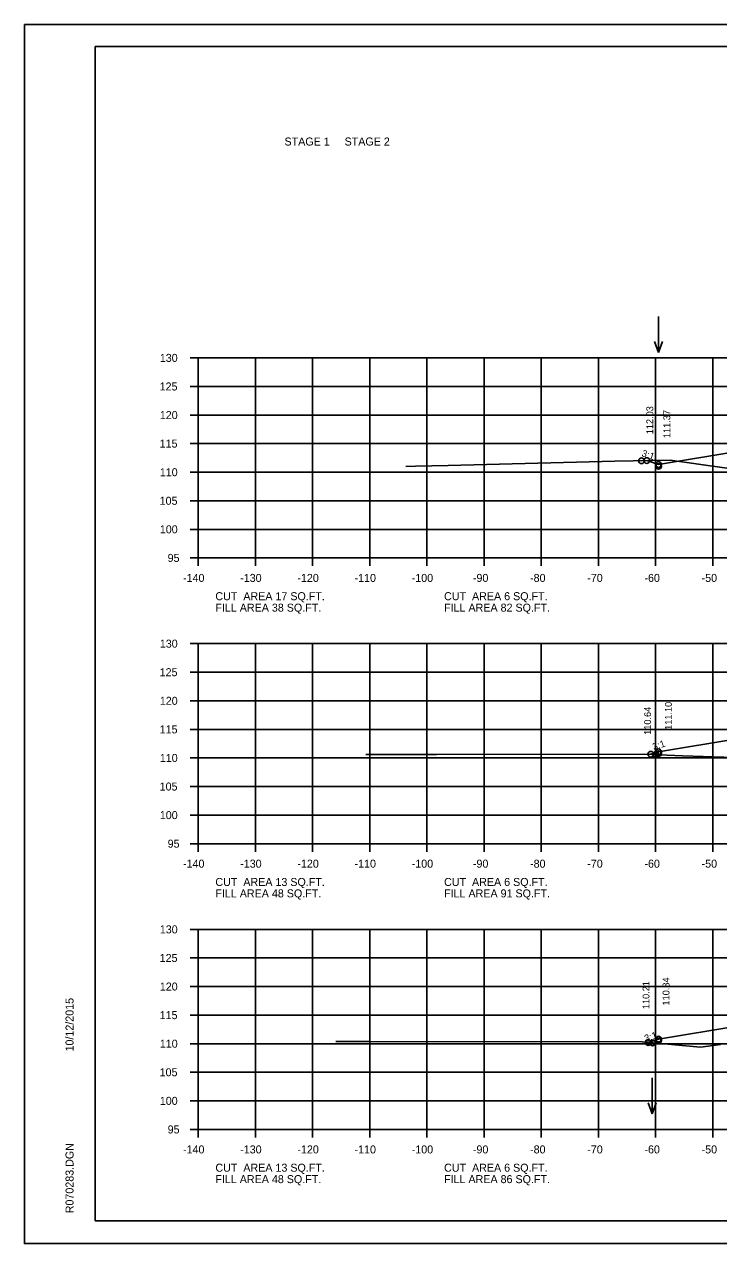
# Model space of a CAD drawing. Extents: x 1175611 to 1176402, y -433344 to -416213.
# Drawn here: x 1175610.6 to 1175732, y -421823.3 to -421609.9 of the extents above; entities that cross this region are included whole.
import ezdxf

# ---------------------------------------------------------------- set-up
doc = ezdxf.new("R2010")
doc.units = 0
for name, color, linetype in [('Default', 7, 'Continuous'), ('R_Axis', 7, 'Continuous'), ('R_Axis Annot', 7, 'Continuous'), ('R_Border', 7, 'Continuous'), ('R_Exist Surface', 7, 'Continuous'), ('R_Fin Surface', 7, 'Continuous'), ('R_Grid', 7, 'Continuous'), ('R_No Plot', 7, 'Continuous'), ('R_Water Annot', 7, 'Continuous'), ('R_Xsect Elev', 7, 'Continuous'), ('R_Xsect Slope', 7, 'Continuous')]:
    doc.layers.add(name, color=color, linetype=linetype)

msp = doc.modelspace()

# ---------------------------------------------------------------- linework, layer by layer
at = {"layer": 'R_Axis'}
for p, q in [((1175639.57, -421668.3), (1175640.97, -421668.3)), ((1175640.97, -421703.3), (1175640.97, -421668.3)), ((1175639.57, -421673.3), (1175640.97, -421673.3)), ((1175639.57, -421678.3), (1175640.97, -421678.3)), ((1175639.57, -421683.3), (1175640.97, -421683.3)), ((1175639.57, -421688.3), (1175640.97, -421688.3)), ((1175639.57, -421693.3), (1175640.97, -421693.3)), ((1175639.57, -421698.3), (1175640.97, -421698.3)), ((1175639.57, -421703.3), (1175640.97, -421703.3)), ((1175640.97, -421703.3), (1175920.97, -421703.3)), ((1175640.97, -421704.7), (1175640.97, -421703.3)), ((1175650.97, -421704.7), (1175650.97, -421703.3)), ((1175660.97, -421704.7), (1175660.97, -421703.3)), ((1175670.97, -421704.7), (1175670.97, -421703.3)), ((1175680.97, -421704.7), (1175680.97, -421703.3)), ((1175690.97, -421704.7), (1175690.97, -421703.3)), ((1175700.97, -421704.7), (1175700.97, -421703.3)), ((1175710.97, -421704.7), (1175710.97, -421703.3)), ((1175720.97, -421704.7), (1175720.97, -421703.3)), ((1175730.97, -421704.7), (1175730.97, -421703.3)), ((1175639.57, -421718.3), (1175640.97, -421718.3)), ((1175640.97, -421753.3), (1175640.97, -421718.3)), ((1175639.57, -421723.3), (1175640.97, -421723.3)), ((1175639.57, -421728.3), (1175640.97, -421728.3)), ((1175639.57, -421733.3), (1175640.97, -421733.3)), ((1175639.57, -421738.3), (1175640.97, -421738.3)), ((1175639.57, -421743.3), (1175640.97, -421743.3)), ((1175639.57, -421748.3), (1175640.97, -421748.3)), ((1175639.57, -421753.3), (1175640.97, -421753.3)), ((1175640.97, -421753.3), (1175920.97, -421753.3)), ((1175640.97, -421754.7), (1175640.97, -421753.3)), ((1175650.97, -421754.7), (1175650.97, -421753.3)), ((1175660.97, -421754.7), (1175660.97, -421753.3)), ((1175670.97, -421754.7), (1175670.97, -421753.3)), ((1175680.97, -421754.7), (1175680.97, -421753.3)), ((1175690.97, -421754.7), (1175690.97, -421753.3)), ((1175700.97, -421754.7), (1175700.97, -421753.3)), ((1175710.97, -421754.7), (1175710.97, -421753.3)), ((1175720.97, -421754.7), (1175720.97, -421753.3)), ((1175730.97, -421754.7), (1175730.97, -421753.3)), ((1175639.57, -421768.3), (1175640.97, -421768.3)), ((1175640.97, -421803.3), (1175640.97, -421768.3)), ((1175639.57, -421773.3), (1175640.97, -421773.3)), ((1175639.57, -421778.3), (1175640.97, -421778.3)), ((1175639.57, -421783.3), (1175640.97, -421783.3)), ((1175639.57, -421788.3), (1175640.97, -421788.3)), ((1175639.57, -421793.3), (1175640.97, -421793.3)), ((1175639.57, -421798.3), (1175640.97, -421798.3)), ((1175639.57, -421803.3), (1175640.97, -421803.3)), ((1175640.97, -421803.3), (1175920.97, -421803.3)), ((1175640.97, -421804.7), (1175640.97, -421803.3)), ((1175650.97, -421804.7), (1175650.97, -421803.3)), ((1175660.97, -421804.7), (1175660.97, -421803.3)), ((1175670.97, -421804.7), (1175670.97, -421803.3)), ((1175680.97, -421804.7), (1175680.97, -421803.3)), ((1175690.97, -421804.7), (1175690.97, -421803.3)), ((1175700.97, -421804.7), (1175700.97, -421803.3)), ((1175710.97, -421804.7), (1175710.97, -421803.3)), ((1175720.97, -421804.7), (1175720.97, -421803.3)), ((1175730.97, -421804.7), (1175730.97, -421803.3))]:
    msp.add_line(p, q, dxfattribs=at)
at = {"layer": 'R_Border'}
for p, q in [((1175622.97, -421613.84), (1175939.15, -421613.84)), ((1175622.97, -421819.3), (1175622.97, -421613.84)), ((1175622.97, -421819.3), (1175622.97, -421819.3)), ((1175939.15, -421819.3), (1175622.97, -421819.3))]:
    msp.add_line(p, q, dxfattribs=at)
at = {"layer": 'R_Exist Surface'}
for points in [[(1175677.28, -421687.29), (1175678.96, -421687.26), (1175684.7, -421687.12), (1175713.84, -421686.38), (1175723.49, -421686.18), (1175733.41, -421687.61)], [(1175670.26, -421737.68), (1175670.42, -421737.68), (1175675.91, -421737.68), (1175682.64, -421737.67), (1175718.96, -421737.61), (1175725.69, -421737.92), (1175734.69, -421738.22)], [(1175665.01, -421787.92), (1175670.42, -421787.9), (1175670.5, -421787.9), (1175671.12, -421787.9), (1175718.6, -421787.99), (1175719.28, -421788.06), (1175728.82, -421788.92), (1175731.91, -421788.48), (1175732.3, -421788.42)]]:
    msp.add_lwpolyline(points, dxfattribs=at)
at = {"layer": 'R_Fin Surface'}
for points in [[(1175719.41, -421686.26), (1175721.47, -421686.95), (1175735.2, -421684.66), (1175743.47, -421683.29), (1175749.47, -421683.05), (1175751.47, -421683.01), (1175780.97, -421682.42), (1175810.47, -421683.01), (1175812.47, -421683.05), (1175818.47, -421683.29), (1175826.75, -421684.66), (1175840.47, -421686.95), (1175841.4, -421687.26)], [(1175720.13, -421737.66), (1175721.47, -421737.22), (1175735.2, -421734.93), (1175743.47, -421733.55), (1175749.47, -421733.31), (1175751.47, -421733.27), (1175780.97, -421732.68), (1175810.47, -421733.27), (1175812.47, -421733.31), (1175818.47, -421733.55), (1175826.75, -421734.93), (1175840.47, -421737.22), (1175842.06, -421737.74)], [(1175719.68, -421788.09), (1175721.47, -421787.5), (1175735.2, -421785.21), (1175743.47, -421783.83), (1175749.47, -421783.59), (1175751.47, -421783.55), (1175780.97, -421782.96), (1175810.47, -421783.55), (1175812.47, -421783.59), (1175818.47, -421783.83), (1175826.75, -421785.21), (1175840.47, -421787.5), (1175841.57, -421787.86)]]:
    msp.add_lwpolyline(points, dxfattribs=at)
at = {"layer": 'R_Grid'}
for p, q in [((1175640.97, -421668.3), (1175920.97, -421668.3)), ((1175640.97, -421703.3), (1175640.97, -421668.3)), ((1175650.97, -421703.3), (1175650.97, -421668.3)), ((1175660.97, -421703.3), (1175660.97, -421668.3)), ((1175670.97, -421703.3), (1175670.97, -421668.3)), ((1175680.97, -421703.3), (1175680.97, -421668.3)), ((1175690.97, -421703.3), (1175690.97, -421668.3)), ((1175700.97, -421703.3), (1175700.97, -421668.3)), ((1175710.97, -421703.3), (1175710.97, -421668.3)), ((1175720.97, -421703.3), (1175720.97, -421668.3)), ((1175730.97, -421703.3), (1175730.97, -421668.3)), ((1175640.97, -421673.3), (1175920.97, -421673.3)), ((1175640.97, -421678.3), (1175920.97, -421678.3)), ((1175640.97, -421683.3), (1175920.97, -421683.3)), ((1175640.97, -421688.3), (1175920.97, -421688.3)), ((1175640.97, -421693.3), (1175920.97, -421693.3)), ((1175640.97, -421698.3), (1175920.97, -421698.3)), ((1175640.97, -421703.3), (1175920.97, -421703.3)), ((1175640.97, -421718.3), (1175920.97, -421718.3)), ((1175640.97, -421753.3), (1175640.97, -421718.3)), ((1175650.97, -421753.3), (1175650.97, -421718.3)), ((1175660.97, -421753.3), (1175660.97, -421718.3)), ((1175670.97, -421753.3), (1175670.97, -421718.3)), ((1175680.97, -421753.3), (1175680.97, -421718.3)), ((1175690.97, -421753.3), (1175690.97, -421718.3)), ((1175700.97, -421753.3), (1175700.97, -421718.3)), ((1175710.97, -421753.3), (1175710.97, -421718.3)), ((1175720.97, -421753.3), (1175720.97, -421718.3)), ((1175730.97, -421753.3), (1175730.97, -421718.3)), ((1175640.97, -421723.3), (1175920.97, -421723.3)), ((1175640.97, -421728.3), (1175920.97, -421728.3)), ((1175640.97, -421733.3), (1175920.97, -421733.3)), ((1175640.97, -421738.3), (1175920.97, -421738.3)), ((1175640.97, -421743.3), (1175920.97, -421743.3)), ((1175640.97, -421748.3), (1175920.97, -421748.3)), ((1175640.97, -421753.3), (1175920.97, -421753.3)), ((1175640.97, -421768.3), (1175920.97, -421768.3)), ((1175640.97, -421803.3), (1175640.97, -421768.3)), ((1175650.97, -421803.3), (1175650.97, -421768.3)), ((1175660.97, -421803.3), (1175660.97, -421768.3)), ((1175670.97, -421803.3), (1175670.97, -421768.3)), ((1175680.97, -421803.3), (1175680.97, -421768.3)), ((1175690.97, -421803.3), (1175690.97, -421768.3)), ((1175700.97, -421803.3), (1175700.97, -421768.3)), ((1175710.97, -421803.3), (1175710.97, -421768.3)), ((1175720.97, -421803.3), (1175720.97, -421768.3)), ((1175730.97, -421803.3), (1175730.97, -421768.3)), ((1175640.97, -421773.3), (1175920.97, -421773.3)), ((1175640.97, -421778.3), (1175920.97, -421778.3)), ((1175640.97, -421783.3), (1175920.97, -421783.3)), ((1175640.97, -421788.3), (1175920.97, -421788.3)), ((1175640.97, -421793.3), (1175920.97, -421793.3)), ((1175640.97, -421798.3), (1175920.97, -421798.3)), ((1175640.97, -421803.3), (1175920.97, -421803.3))]:
    msp.add_line(p, q, dxfattribs=at)
at = {"layer": 'R_No Plot'}
for p, q in [((1175610.57, -421609.94), (1175943.91, -421609.94)), ((1175610.57, -421823.28), (1175943.91, -421823.28))]:
    msp.add_line(p, q, dxfattribs=at)
msp.add_lwpolyline([(1175610.57, -421609.94), (1175943.91, -421609.94), (1175943.91, -421823.28), (1175610.57, -421823.28)], close=True, dxfattribs=at)
for centre in [(1175718.49, -421686.29), (1175719.41, -421686.26), (1175719.41, -421686.26), (1175721.47, -421686.95), (1175721.47, -421687.28), (1175720.13, -421737.66), (1175720.13, -421737.66), (1175721, -421737.7), (1175721, -421737.7), (1175721.47, -421737.22), (1175721.47, -421737.55), (1175719.68, -421788.09), (1175719.68, -421788.09), (1175721.47, -421787.5), (1175721.47, -421787.81), (1175720.43, -421788.16)]:
    msp.add_circle(centre, 0.5, dxfattribs=at)
at = {"layer": 'R_Water Annot'}
for p, q in [((1175721.46, -421661.07), (1175721.46, -421667.36)), ((1175721.46, -421667.36), (1175720.76, -421665.43)), ((1175721.46, -421667.36), (1175722.16, -421665.43)), ((1175720.35, -421794.29), (1175720.35, -421800.58)), ((1175720.35, -421800.58), (1175719.65, -421798.65)), ((1175720.35, -421800.58), (1175721.05, -421798.65))]:
    msp.add_line(p, q, dxfattribs=at)

# ---------------------------------------------------------------- texts
at = {"layer": 'Default'}
for s, p in [('STAGE 1     STAGE 2', (1175656.06, -421631.14)), ('CUT  AREA 17 SQ.FT.', (1175643.97, -421710.7)), ('CUT  AREA 6 SQ.FT.', (1175683.97, -421710.7)), ('FILL AREA 38 SQ.FT.', (1175643.97, -421712.7)), ('FILL AREA 82 SQ.FT.', (1175683.97, -421712.7)), ('CUT  AREA 13 SQ.FT.', (1175643.97, -421760.7)), ('CUT  AREA 6 SQ.FT.', (1175683.97, -421760.7)), ('FILL AREA 48 SQ.FT.', (1175643.97, -421762.7)), ('FILL AREA 91 SQ.FT.', (1175683.97, -421762.7)), ('CUT  AREA 13 SQ.FT.', (1175643.97, -421810.7)), ('CUT  AREA 6 SQ.FT.', (1175683.97, -421810.7)), ('FILL AREA 48 SQ.FT.', (1175643.97, -421812.7)), ('FILL AREA 86 SQ.FT.', (1175683.97, -421812.7))]:
    msp.add_text(s, height=1.4, dxfattribs=at).set_placement(p)
at = {"layer": 'R_Axis Annot'}
for s, p in [('130', (1175634.25, -421669)), ('125', (1175634.22, -421674)), ('120', (1175634.25, -421679)), ('115', (1175634.22, -421684)), ('110', (1175634.25, -421689)), ('105', (1175634.22, -421694)), ('100', (1175634.25, -421699)), ('95', (1175635.62, -421704)), ('-140', (1175638.31, -421707.5)), ('-130', (1175648.31, -421707.5)), ('-120', (1175658.31, -421707.5)), ('-110', (1175668.31, -421707.5)), ('-100', (1175678.31, -421707.5)), ('-90', (1175689.01, -421707.5)), ('-80', (1175699.01, -421707.5)), ('-70', (1175709.01, -421707.5)), ('-60', (1175719.01, -421707.5)), ('-50', (1175729.01, -421707.5)), ('130', (1175634.25, -421719)), ('125', (1175634.22, -421724)), ('120', (1175634.25, -421729)), ('115', (1175634.22, -421734)), ('110', (1175634.25, -421739)), ('105', (1175634.22, -421744)), ('100', (1175634.25, -421749)), ('95', (1175635.62, -421754)), ('-140', (1175638.31, -421757.5)), ('-130', (1175648.31, -421757.5)), ('-120', (1175658.31, -421757.5)), ('-110', (1175668.31, -421757.5)), ('-100', (1175678.31, -421757.5)), ('-90', (1175689.01, -421757.5)), ('-80', (1175699.01, -421757.5)), ('-70', (1175709.01, -421757.5)), ('-60', (1175719.01, -421757.5)), ('-50', (1175729.01, -421757.5)), ('130', (1175634.25, -421769)), ('125', (1175634.22, -421774)), ('120', (1175634.25, -421779)), ('115', (1175634.22, -421784)), ('110', (1175634.25, -421789)), ('105', (1175634.22, -421794)), ('100', (1175634.25, -421799)), ('95', (1175635.62, -421804)), ('-140', (1175638.31, -421807.5)), ('-130', (1175648.31, -421807.5)), ('-120', (1175658.31, -421807.5)), ('-110', (1175668.31, -421807.5)), ('-100', (1175678.31, -421807.5)), ('-90', (1175689.01, -421807.5)), ('-80', (1175699.01, -421807.5)), ('-70', (1175709.01, -421807.5)), ('-60', (1175719.01, -421807.5)), ('-50', (1175729.01, -421807.5))]:
    msp.add_text(s, height=1.4, dxfattribs=at).set_placement(p)
at = {"layer": 'R_Border'}
for s, p in [('10/12/2015', (1175619.16, -421789.66)), ('R070283.DGN', (1175619.16, -421817.97))]:
    msp.add_text(s, height=1.4, rotation=90, dxfattribs=at).set_placement(p)
at = {"layer": 'R_Xsect Elev'}
for s, p in [('112.03', (1175720.55, -421681.66)), ('111.37', (1175723.53, -421682.33)), ('110.64', (1175720.16, -421734.26)), ('111.10', (1175723.8, -421733.39)), ('110.84', (1175723.39, -421781.62)), ('110.21', (1175719.89, -421782.25))]:
    msp.add_text(s, height=1.2, rotation=90, dxfattribs=at).set_placement(p)
at = {"layer": 'R_Xsect Slope'}
for rotation, p in [(341.5651, (1175718.43, -421685.48)), (18.4349, (1175720.64, -421736.97)), (18.4349, (1175719.23, -421787.99))]:
    msp.add_text('3:1', height=1.2, rotation=rotation, dxfattribs=at).set_placement(p)

doc.saveas('drawing.dxf')
